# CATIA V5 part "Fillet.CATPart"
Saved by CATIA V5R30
Part number: Part1
Bounding box of the stored display mesh (mm): x -37.5 to 37.5, y -94 to 94, z -94 to 94
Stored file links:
  D:\PROJECTS\CATIA V56R 2020\Resources\Parts File\c17_catia_v6_6r2020_prt\Fillet.CATPart
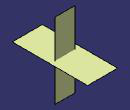
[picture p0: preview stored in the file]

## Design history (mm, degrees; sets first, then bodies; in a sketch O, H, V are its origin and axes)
Body1 (main body)
  Sketch1 on xy-plane, origin (0, 0, 0), H (1, 0, 0), V (0, 1, 0)
    line L1 (-25, 0) -> (25, 0)
    point P1 (-25, 0)
    point P2 (25, 0)
    length L1 = 50
    coincidence: P1 H
    horizontal: L1 H
    symmetry: P1 P2 V
  Sketch2 on zx-plane, origin (0, 0, 0), H (-1, 0, 0), V (0, 0, 1)
    line L1 (-37.5, 0) -> (37.5, 0)
    point P1 (-37.5, 0)
    point P2 (37.5, 0)
    length L1 = 75
    coincidence: P1 H
    horizontal: L1 H
    symmetry: P2 P1 V
  Extrude1: Element1 Sketch2, Lim1 94, Lim2 94
  Extrude2: Element1 Sketch1, Lim1 94, Lim2 94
